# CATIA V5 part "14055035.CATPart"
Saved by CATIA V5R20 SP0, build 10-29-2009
Part number: 14055035
Definition: NONE
Nomenclature: 14055035
Source: Unknown
Description: 14055035
Bounding box of the stored display mesh (mm): x -17.5 to 70, y -41.5 to 31.6, z -31.6 to 31.6
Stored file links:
  C:\Users\Utente\Desktop\IO LAVORO\3D X SITO CF\X SITO\PLASTICA\RF2\14055035.CATPart
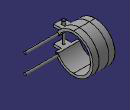
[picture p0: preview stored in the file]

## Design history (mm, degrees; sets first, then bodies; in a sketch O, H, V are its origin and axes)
Body1 "14055035" (main body)
  Solid1: solid without history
